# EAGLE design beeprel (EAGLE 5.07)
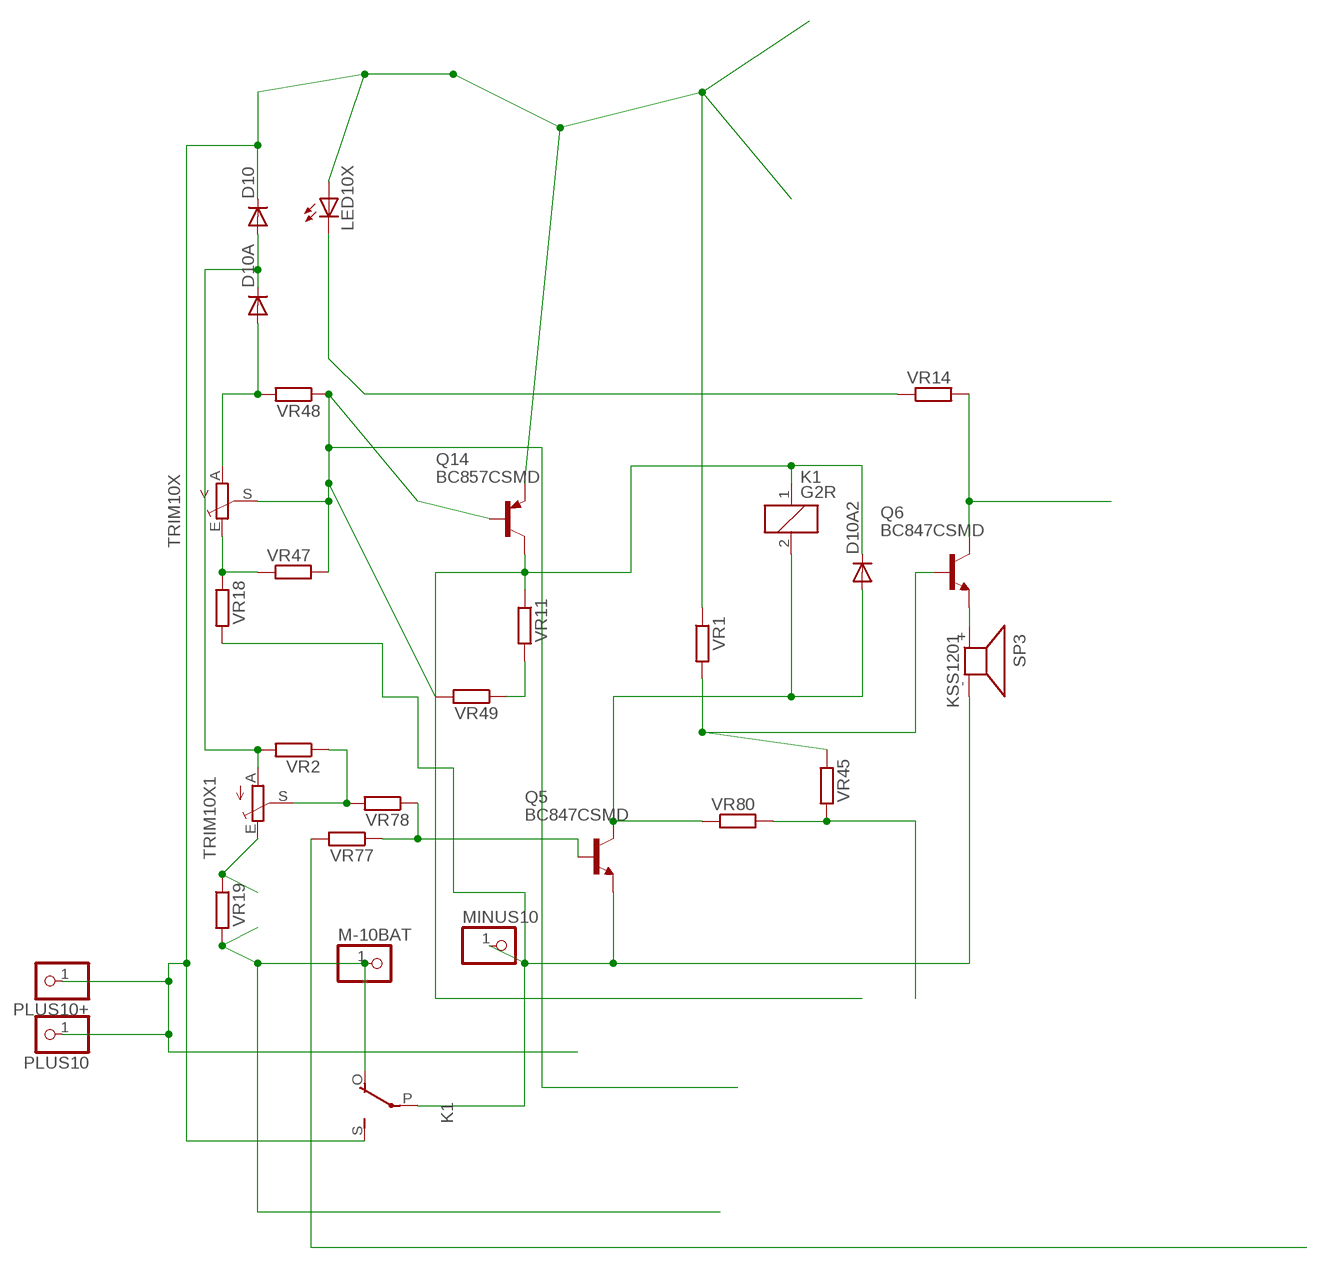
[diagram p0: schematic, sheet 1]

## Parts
D10  DIODE-MINIMELF  [MINIMELF]
D10A  DIODE-MINIMELF  [MINIMELF]
D10A2  DIODE-MINIMELF  [MINIMELF]
K1  G2R  [G2R]
LED10X  LEDCHIPLED_1206  [CHIPLED_1206]
M-10BAT  PINHD-1X11X0.4  [1X01]
MINUS10  PINHD-1X14.5MM  [1X4MM5]
PLUS10  PINHD-1X14.5MM  [1X4MM5]
PLUS10+  PINHD-1X11X0.4  [1X01]
Q5  BC847CSMD  [SOT23]
Q6  BC847CSMD  [SOT23]
Q14  BC857CSMD  [SOT23-BEC]
SP3  KSS1201  [KSS1201]
TRIM10X  TRIM_EU-S64W  [S64W]
TRIM10X1  TRIM_EU-S64W  [S64W]
VR1  R-EU_R0805  [R0805]
VR2  R-EU_R0603  [R0603]
VR11  R-EU_R0805  [R0805]
VR14  R-EU_R0805  [R0805]
VR18  R-EU_R1206  [R1206]
VR19  R-EU_R1206  [R1206]
VR45  R-EU_R0805  [R0805]
VR47  R-EU_R0603  [R0603]
VR48  R-EU_R0805  [R0805]
VR49  R-EU_R0805  [R0805]
VR77  R-EU_R0805  [R0805]
VR78  R-EU_R0805  [R0805]
VR80  R-EU_R0805  [R0805]

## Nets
B: Q14.B TRIM10X.S VR47.2 VR48.1 VR49.2
B2: VR77.2
E10: K1.P(2:P) MINUS10.1 Q5.2(E) SP3.- VR18.2
GP3: Q6.2(E) SP3.+
N$11: LED10X.C VR14.1
N$15: D10A2.C K1.1 Q14.C VR11.1
N$22: TRIM10X1.S VR2.1 VR78.2
N$24: TRIM10X1.E VR19.1
N$25: VR11.2 VR49.1
N$128: TRIM10X.E VR18.1 VR47.1
N$138: VR45.2 VR80.2
N$146: Q6.1(B) VR1.2 VR45.1
N$168: Q5.1(B) VR77.1 VR78.1
N$169: D10A2.A K1.2 Q5.3(C) VR80.1
PLUS11: D10.C K1.S(2:S) LED10X.A PLUS10+.1 PLUS10.1 Q14.E VR1.1
Q10C: Q6.3(C) VR14.2
VSS: K1.O(2:O) M-10BAT.1 VR19.2
Z1V: D10.A D10A.C TRIM10X1.A VR2.2
Z2V: D10A.A TRIM10X.A VR48.2

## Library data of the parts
D10 D10A D10A2 = diode:DIODE-: DIODE
K1 = relay:G2R: RELAY 1 x switch, Omron
LED10X = led:LED: LED
M-10BAT MINUS10 PLUS10 PLUS10+ = pinhead:PINHD-1X1: PIN HEADER
Q5 Q6 = transistor-npn:BC847*: NPN Transistor
Q14 = transistor-pnp:BC857*: PNP Transistror
SP3 = buzzer:KSS1201: SPEAKER
TRIM10X TRIM10X1 = pot:TRIM_EU-: POTENTIOMETER
VR1 VR2 VR11 VR14 VR18 VR19 VR45 VR47-VR49 VR77 VR78 VR80 = rcl-2:R-EU_: RESISTOR, European symbol

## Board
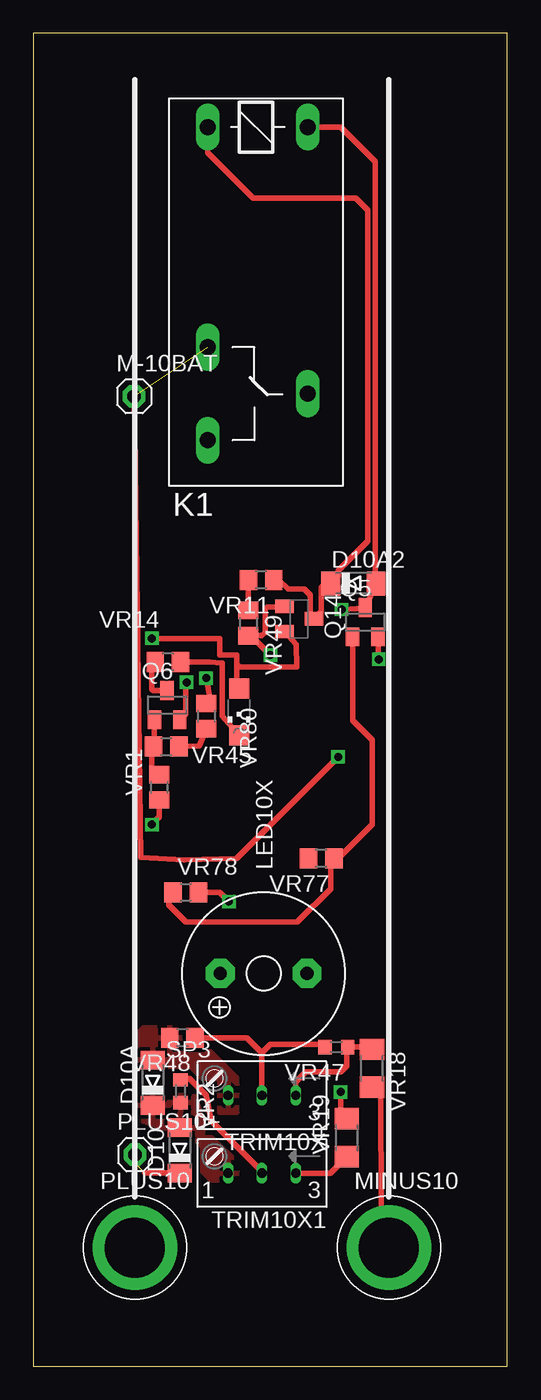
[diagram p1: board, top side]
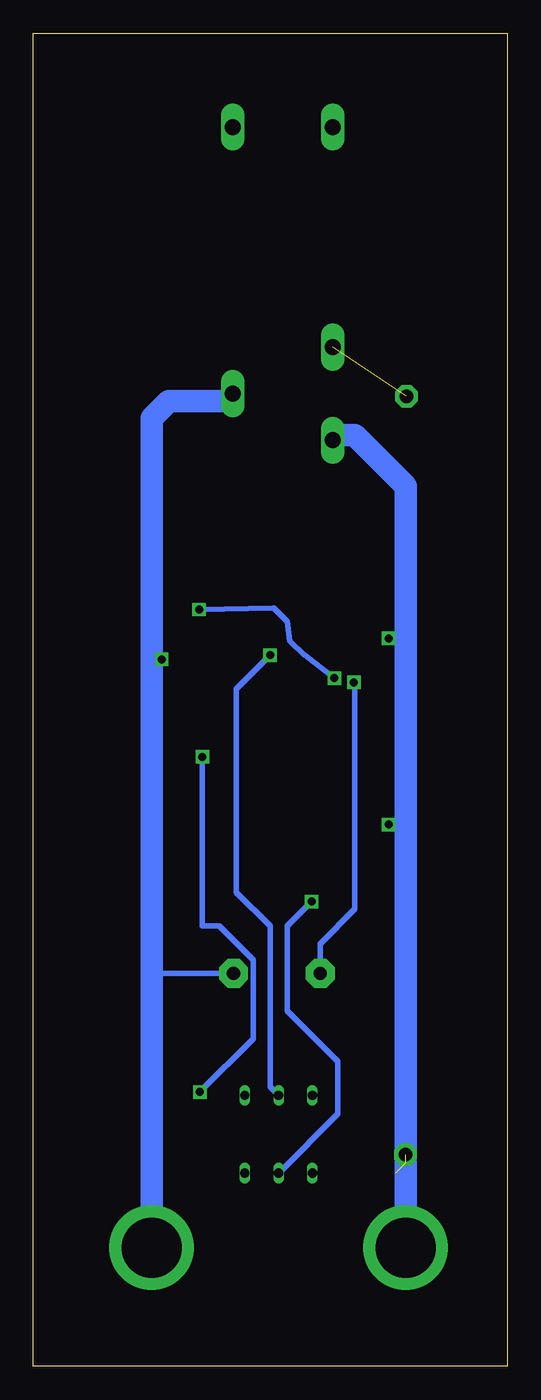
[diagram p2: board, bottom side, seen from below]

Size 35.54 x 100 mm. Coordinates in mm from the lower left corner, seen from the top.
Outline: 0,0 35.54,0 35.54,100 0,100 0,0
Copper layers (1*16): Top 0.035mm / dielectric 1.5mm / Bottom 0.035mm
Design rules "default": minimum track width 10mil, minimum drill 20mil, track to track 8mil, track to pad 8mil, pad to pad 8mil, via to via 8mil, smd to smd 8mil, copper to edge 40mil, drill to drill 8mil, minimum pad ring 1mil, minimum via ring 8mil, stop-mask expansion 4mil, vias tented up to drill 0mil, thermal gap 10mil

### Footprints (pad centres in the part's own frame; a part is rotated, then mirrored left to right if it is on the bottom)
MINIMELF = smd 1.4 x 1.8: A 1.7,0; C -1.7,0
G2R = drill 1.2 pad 1.778 long: 1 -2.54,-3.683; 2 -2.54,3.81; O 13.97,-3.683; P 17.45,3.81; S 20.955,-3.683
CHIPLED_1206 = smd 1.5 x 1.5: A 0,-1.75; C 0,1.75
1X01 = drill 1 pad 1.676 octagon: 1 0,0
1X4MM5 = drill 4.5 pad 6.35 round: 1 0,0
SOT23 = smd 1 x 1.4: 1 -0.95,-1.1; 2 0.95,-1.1; 3 0,1.1
SOT23-BEC = smd 1 x 1.4: B -0.95,-1.1; C 0,1.1; E 0.95,-1.1
KSS1201 = drill 1 pad 2.159 octagon: + 3.251,0; - -3.251,0
S64W = drill 0.7 long: A 2.54,1.27; E -2.54,1.27; S 0,1.27
R0805 = smd 1.3 x 1.5: 1 -0.95,0; 2 0.95,0
R0603 = smd 1 x 1.1: 1 -0.85,0; 2 0.85,0
R1206 = smd 1.6 x 1.803: 1 -1.422,0; 2 1.422,0

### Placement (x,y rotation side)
D10  10.99,16.19 90 top
D10A  8.95,21.27 90 top
D10A2  24,58.74 0 top
K1  16.76,90.42 270 top
LED10X  15.43,49.09 180 top
M-10BAT  7.56,72.77 0 top
MINUS10  26.67,8.89 0 top
PLUS10  7.62,8.89 0 top
PLUS10+  7.62,15.88 0 top
Q5  24.89,55.82 0 top
Q6  10.03,49.59 0 top
Q14  19.94,56.07 270 top
SP3  17.27,29.46 180 top
TRIM10X  17.14,21.59 180 top
TRIM10X1  17.14,15.75 180 top
VR1  9.46,43.43 90 top
VR2  11.05,20.64 270 top
VR11  17.08,58.99 180 top
VR14  10.1,52.83 180 top
VR18  25.4,22.35 270 top
VR19  23.5,17.14 90 top
VR45  9.97,46.48 0 top
VR47  22.73,23.94 180 top
VR48  11.18,24.64 180 top
VR49  16.13,55.75 270 top
VR77  21.59,38.1 180 top
VR78  11.43,35.56 0 top
VR80  12.97,48.77 270 top

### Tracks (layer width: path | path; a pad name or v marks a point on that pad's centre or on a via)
B  (via drill 0.6)
  Top 0.406: VR48.1 16,24.64 17.14,23.5 | 17.14,23.5 TRIM10X.S | 17.14,23.5 17.78,24.13 21.69,24.13 VR47.2 | Q14.B 18.78,56.96 17.53,56.96 17.4,56.83 17.4,55.05 17.15,54.8 VR49.2 16.32,54.8 v17.78,53.34
  Bottom 0.406: v17.78,53.34 20.32,50.8 20.32,35.56 17.78,33.02 17.78,20.95 TRIM10X.S
E10  (via drill 0.6)
  Top 0.406: VR18.2 26.06,20.93 26.1,11.3 MINUS10.1 | v25.91,53.02 Q5.2
  Bottom 0.406: SP3.- 26.42,29.46 26.67,29.21 | 26.67,53.34 v25.91,53.02
  Bottom 1.676: MINUS10.1 26.67,29.21 26.67,53.34 26.67,71.12 25.4,72.39 21.16,72.39 K1.P
GP3  (via drill 0.6)
  Top 0.406: v11.49,51.31 11.49,51.24 11.43,50.8 11.43,48.94 Q6.2
  Bottom 0.406: SP3.+ 14.02,31.7 11.43,34.29 11.43,50.86 v11.49,51.31
N$11
  Top 0.406: VR14.1 13.21,52.83 14.16,52.77 14.16,48.8 LED10X.C
N$15
  Top 0.406: VR11.1 18.41,58.99 19.11,58.29 20.32,58.29 20.77,57.85 20.77,56.34 Q14.C 21.59,56.62 21.59,58.42 21.91,58.74 D10A2.C 22.86,59.29 22.86,59.69 25.08,61.91 25.08,86.74 24.19,87.63 16.51,87.63 13.08,91.06 K1.1
N$22  (via drill 0.6)
  Top 0.406: TRIM10X1.S 17.14,14.61 13.34,18.41 12.95,20.32 11.68,21.59 11.15,21.59 VR2.1 | VR78.2 13.97,35.56 v14.67,34.86
  Bottom 0.406: v14.67,34.86 16.51,33.02 16.51,26.67 12.7,22.86 12.7,18.92 TRIM10X1.S
N$24
  Top 0.406: TRIM10X1.E 22.25,14.48 VR19.1
N$25
  Top 0.406: VR49.1 VR11.2
N$128
  Top 0.406: TRIM10X.E 19.68,21.34 20.45,22.1 23.05,22.1 23.5,22.54 23.5,23.85 VR47.1 25.23,23.94 VR18.1
N$138
  Top 0.406: VR45.2 12.45,46.55 VR80.2
N$146
  Top 0.406: Q6.1 9.08,47.18 8.89,46.99 | 8.89,46.99 8.89,44.96 VR1.2 | VR45.1 9.02,46.86 8.89,46.99
N$168
  Top 0.406: VR78.1 10.16,35.56 10.16,34.61 11.43,33.34 19.81,33.34 22.29,35.81 22.29,37.85 VR77.1 22.86,38.1 25.4,40.64 25.4,46.99 23.94,48.45 Q5.1
N$169  (via drill 0.6)
  Top 0.406: v23.11,56.77 24.28,56.85 Q5.3 D10A2.A 25.65,58.79 25.65,90.36 23.05,92.96 K1.2 | v12.95,51.63 13.27,50.02 VR80.1
  Bottom 0.406: v23.11,56.77 17.53,56.9 16.51,55.88 16.32,54.42 15.24,53.34 15.18,53.34 v12.95,51.63
PLUS11  (via drill 0.6)  (2 unrouted)
  Top 0.406: 8.37,14.49 D10.C | VR1.1 9.46,41.21 v8.89,40.64 | LED10X.A 15.24,50.84 15.24,52.64 | 15.24,52.64 15.24,53.34 13.97,53.34 13.97,54.61 v8.89,54.61 | Q14.E 19.73,54.15 19.75,52.45 15.43,52.45 15.24,52.64
  Bottom 0.406: 7.62,40.64 v8.89,40.64 | 7.62,54.61 v8.89,54.61
  Bottom 1.676: PLUS10+.1 7.62,40.64 7.62,54.61 7.62,66.04 11.43,69.85 12.7,69.85 K1.S | PLUS10.1 7.62,15.24
Q10C
  Top 0.406: Q6.3 9,50.69 8.89,50.8 8.89,52.58 VR14.2
VSS  (via drill 0.6)  (1 unrouted)
  Top 0.406: M-10BAT.1 8.06,38.16 11.3,37.97 15.24,38.1 v22.86,45.72 | v23.05,20.57 23.05,19.01 VR19.2
  Bottom 0.406: v22.86,45.72 22.86,33.02 21.59,33.02 19.05,30.48 19.05,24.57 v23.05,20.57
Z1V
  pour Top (isolate 0.305): 7.62,20.32 12.06,20.32 12.7,18.41 12.7,17.14 13.34,17.14 15.24,15.24 15.24,13.97 13.34,13.97 12.7,14.61 12.7,16.51 11.43,17.78 10.16,17.78 8.26,18.41 7.62,19.05
Z2V
  pour Top (isolate 0.305): 7.62,22.86 7.62,24.77 8.26,25.4 11.43,25.4 15.24,21.59 15.24,19.05 13.97,19.05 13.97,21.59 10.16,21.59 10.16,22.86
